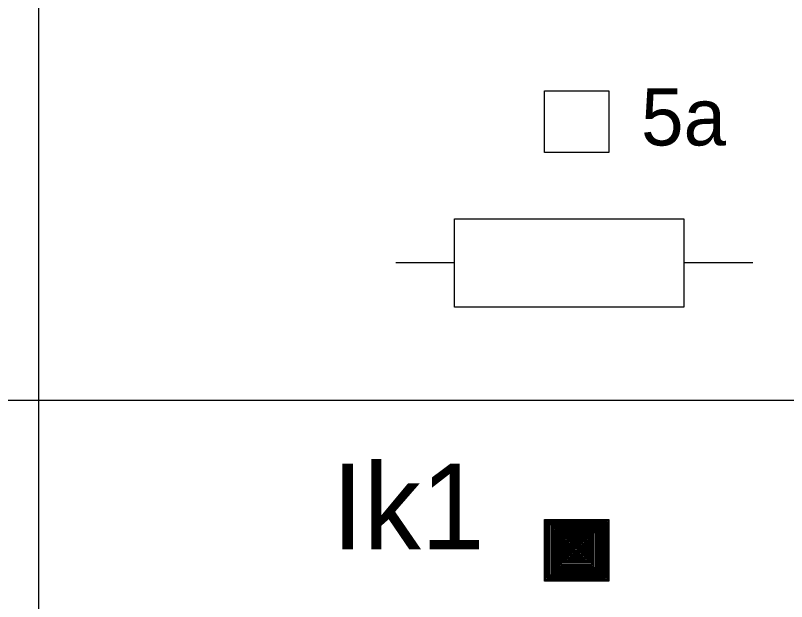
# Model space of a CAD drawing. Extents: x -28 to 822, y 61 to 665.
# Drawn here: x 82.31 to 109.29, y 299.69 to 320.2 of the extents above; entities that cross this region are included whole.
import ezdxf

# ---------------------------------------------------------------- set-up
doc = ezdxf.new("R2010")
doc.units = 0
doc.layers.add('KOLEJIŠTĚ', color=7, linetype='Continuous')

msp = doc.modelspace()

# ---------------------------------------------------------------- linework, layer by layer
for p, q in [((83.116, 336.738), (83.116, 111.738)), ((97.669, 311.546), (95.616, 311.546)), ((108.116, 311.546), (105.693, 311.546)), ((5.068, 306.738), (540.616, 306.738))]:
    msp.add_line(p, q)
for points in [[(103.075, 315.4), (100.821, 315.4), (100.821, 317.565), (103.075, 317.565)], [(105.693, 309.992), (97.669, 309.992), (97.669, 313.086), (105.693, 313.086)], [(103.075, 300.4), (100.821, 300.4), (100.821, 302.565), (103.075, 302.565)], [(103.04, 300.435), (100.841, 300.435), (100.841, 302.534), (103.04, 302.534)], [(102.999, 300.476), (100.874, 300.476), (100.874, 302.494), (102.999, 302.494)], [(102.951, 300.516), (100.915, 300.516), (100.915, 302.461), (102.951, 302.461)], [(102.918, 300.549), (100.947, 300.549), (100.947, 302.437), (102.918, 302.437)], [(102.886, 300.581), (100.988, 300.581), (100.988, 302.413), (102.886, 302.413)], [(102.845, 300.614), (101.012, 300.614), (101.012, 302.38), (102.845, 302.38)], [(102.813, 300.646), (101.069, 300.646), (101.069, 302.348), (102.813, 302.348)], [(102.788, 300.67), (101.093, 300.67), (101.093, 302.316), (102.788, 302.316)], [(102.748, 300.711), (101.117, 300.711), (101.117, 302.283), (102.748, 302.283)], [(102.715, 300.743), (101.158, 300.743), (101.158, 302.243), (102.715, 302.243)], [(102.683, 300.776), (101.198, 300.776), (101.198, 302.202), (102.683, 302.202)], [(102.651, 300.808), (101.231, 300.808), (101.231, 302.17), (102.651, 302.17)], [(102.618, 300.84), (101.263, 300.84), (101.263, 302.137), (102.618, 302.137)], [(102.578, 300.873), (101.304, 300.873), (101.304, 302.105), (102.578, 302.105)], [(102.529, 300.905), (101.353, 300.905), (101.353, 302.072), (102.529, 302.072)], [(102.496, 300.946), (101.385, 300.946), (101.385, 302.04), (102.496, 302.04)], [(102.456, 300.978), (101.426, 300.978), (101.426, 301.999), (102.456, 301.999)], [(102.423, 301.027), (101.466, 301.027), (101.466, 301.967), (102.423, 301.967)], [(102.375, 301.067), (101.515, 301.067), (101.515, 301.935), (102.375, 301.935)], [(102.334, 301.108), (101.547, 301.108), (101.547, 301.902), (102.334, 301.902)], [(102.302, 301.14), (101.588, 301.14), (101.588, 301.862), (102.302, 301.862)], [(102.253, 301.189), (101.628, 301.189), (101.628, 301.829), (102.253, 301.829)], [(102.221, 301.221), (101.669, 301.221), (101.669, 301.789), (102.221, 301.789)], [(102.18, 301.262), (101.718, 301.262), (101.718, 301.748), (102.18, 301.748)], [(102.139, 301.302), (101.758, 301.302), (101.758, 301.716), (102.139, 301.716)], [(102.107, 301.327), (101.783, 301.327), (101.783, 301.675), (102.107, 301.675)], [(102.058, 301.367), (101.815, 301.367), (101.815, 301.643), (102.058, 301.643)], [(102.026, 301.4), (101.839, 301.4), (101.839, 301.61), (102.026, 301.61)], [(101.985, 301.432), (101.872, 301.432), (101.872, 301.578), (101.985, 301.578)], [(101.953, 301.465), (101.896, 301.465), (101.896, 301.546), (101.953, 301.546)]]:
    msp.add_lwpolyline(points, close=True)

# ---------------------------------------------------------------- texts
msp.add_text('5a', height=2).set_placement((104.2, 315.651))
at = {"layer": 'KOLEJIŠTĚ'}
msp.add_text('Ik1', height=3, dxfattribs=at).set_placement((93.375, 301.519))

doc.saveas('drawing.dxf')
